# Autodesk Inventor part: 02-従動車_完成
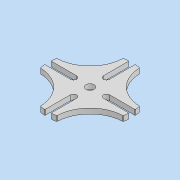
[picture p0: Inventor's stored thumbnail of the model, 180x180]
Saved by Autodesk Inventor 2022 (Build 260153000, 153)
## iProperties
Created: 2021-07
Part Number: 02-従動車_完成
Material: 一般
Document SubType Name: Modeling
Designer: DesignLab
Density: 1 g/cm^3
Appearance: 既定
Author: DesignLab
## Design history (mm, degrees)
sketch "スケッチ1"
  geometry: C1 r 41 at (0, 0); 1 further point
  constraints: 1 centre point, 1 coincident
  dimensions: "d0" = 82 diameter of C1
extrude "押し出し1" new body sketch "スケッチ1" distance "d1" = 5; taper "d2" = 0 deg
sketch "スケッチ2"
  geometry: L1 (0, 16)-(0, 41); L2 (3, 16)-(3, 41); L3 (-3, 41)-(-3, 16); A1 r 3 centre (0, 16) between (-3, 16) and (3, 16); A2 r 3 centre (0, 41) between (3, 41) and (-3, 41); 3 further points
  constraints: 8 end point, 4 point on circle, 4 tangent, 2 centre point, 2 vertical alignment, 1 midpoint, 1 parallel, 1 vertical, 1 other
  dimensions: "d3" = 6 diameter of A2; "d4" = 16 distance of point (0, 0) L1.start
extrude "押し出し2" cut sketch "スケッチ2" extent not by distance; stored distance "d5" = 0; taper "d6" = 0 deg
sketch "スケッチ3"
  geometry: L1 (0, 0)-(41.012, 41.012); L2 (0, 0)-(58, 0); C1 r 33 at (41.012, 41.012)
  constraints: 4 end point, 1 centre point, 1 coincident, 1 equal length, 1 horizontal
  dimensions: "d7" = 58 distance of L1.start L1.end; "d8" = 45 deg angle of L2 L1; "d9" = 33 radius of C1
extrude "押し出し3" cut sketch "スケッチ3" extent not by distance; stored distance "d10" = 0; taper "d11" = 0 deg
chamfer "面取り1" distance "d12" = 0.5; stored, may be unused: second distance "d13" = 2, angle "d14" = 45 deg
pattern_circular "円形状パターン1" dims angle "d16" = 360 deg
hole "穴1" diameter "d20" = 8; stored, may be unused: countersink angle "d24" = 90 deg, drill point angle "d26" = 118 deg; dims "d18" = 10, "d19" = 10, "d21" = 6, "d22" = 4, "d23" = 2, "d25" = 8
node "ソリッド1"
